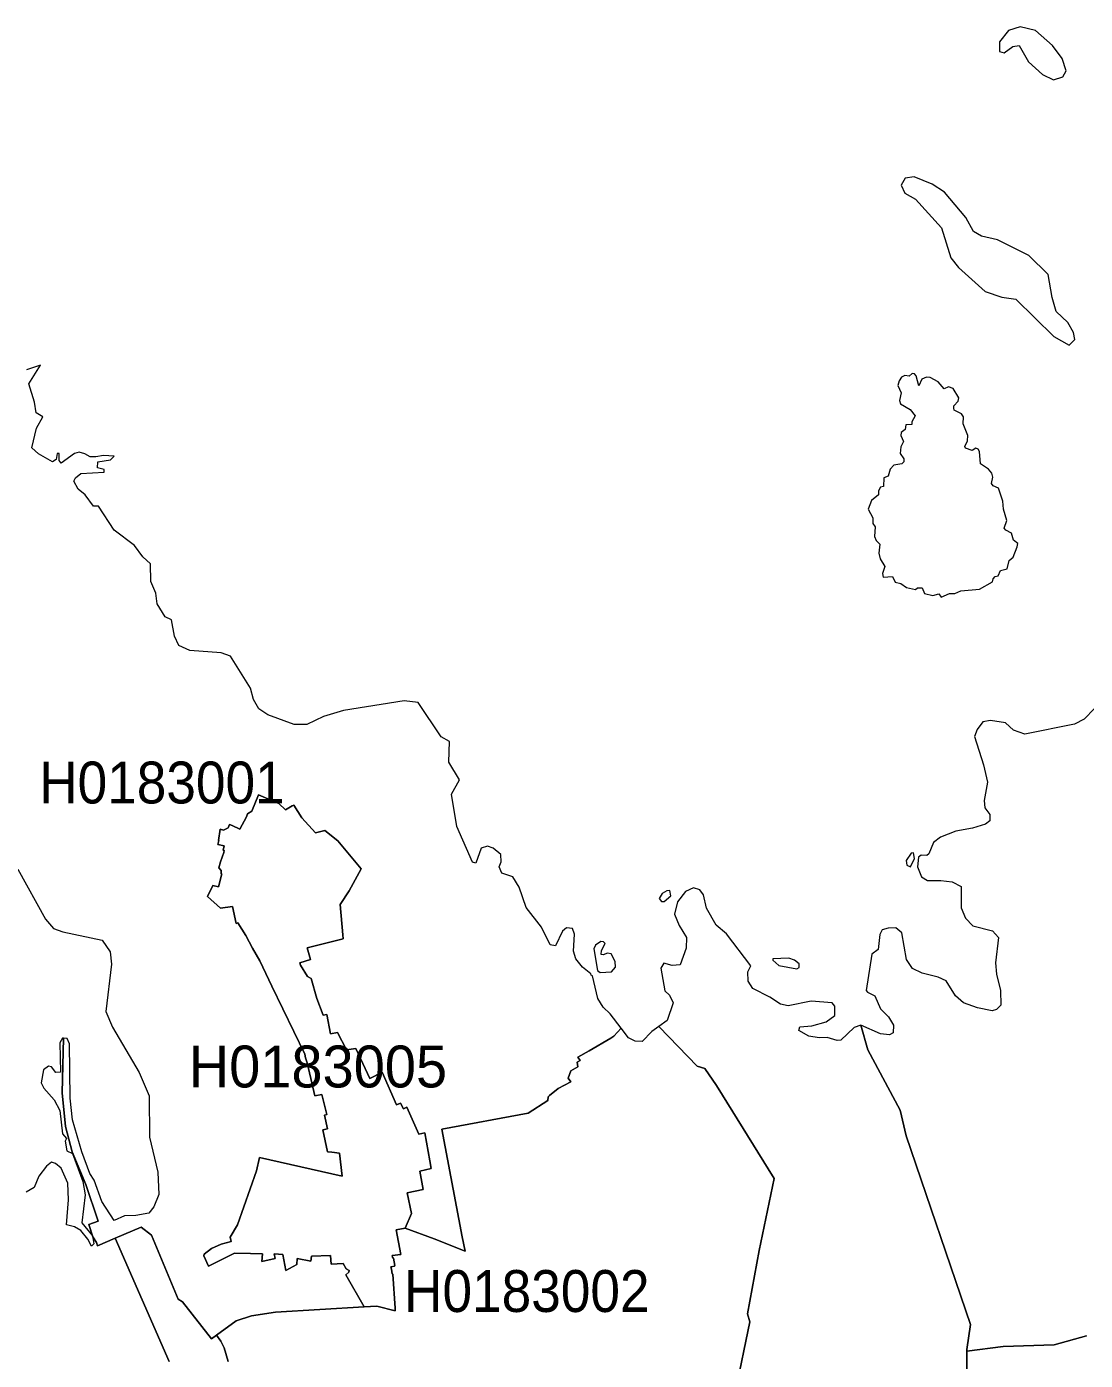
# Model space of a CAD drawing. Extents: x 369010 to 739155, y 6377141 to 6616555.
# Drawn here: x 472785 to 475314, y 6533160 to 6536345 of the extents above; entities that cross this region are included whole.
import ezdxf
from ezdxf.enums import TextEntityAlignment as Align

# ---------------------------------------------------------------- set-up
doc = ezdxf.new("R2010")
doc.units = 0
doc.header["$LTSCALE"] = 40
doc.layers.add('1', color=7, linetype='Continuous', lineweight=13)
doc.layers.add('2', color=7, linetype='Continuous')

msp = doc.modelspace()

# ---------------------------------------------------------------- linework, layer by layer
at = {"layer": '1'}
for points in [[(475194.76, 6536336.3), (475158.18, 6536345.08), (475129.88, 6536336.3), (475108.2, 6536309.16), (475108.2, 6536285.66), (475119.95, 6536282.51), (475140.31, 6536298.07), (475155.7, 6536299.89), (475178.04, 6536261), (475211.31, 6536231.21), (475237.29, 6536218.3), (475259.64, 6536225.09), (475267.58, 6536239.98), (475257.81, 6536268.94), (475235.47, 6536299.89)], [(474904.46, 6535986.43), (474883.44, 6535982.95), (474873.51, 6535966.24), (474882.62, 6535947.87), (474907.77, 6535932.81), (474970, 6535864.45), (474992.02, 6535792.95), (475010.72, 6535769.95), (475074.6, 6535712.85), (475113.99, 6535699.28), (475147.42, 6535693.98), (475238.45, 6535605.11), (475275.03, 6535584.58), (475288.6, 6535598.16), (475285.62, 6535614.87), (475271.88, 6535638.54), (475244.08, 6535664.69), (475234.31, 6535698.12), (475224.38, 6535753.56), (475178.87, 6535798.42), (475103.73, 6535836.32), (475065.66, 6535844.59), (475046.63, 6535856.01), (475028.43, 6535889.44), (474976.79, 6535949.52), (474947.99, 6535969.22)], [(474903.3, 6534372.1), (474897.35, 6534371.11), (474885.27, 6534354.06), (474887.58, 6534342.64), (474896.02, 6534338.51), (474905.46, 6534359.03)], [(474321.39, 6534282.07), (474314.28, 6534281.74), (474302.69, 6534274.95), (474295.57, 6534262.87), (474300.87, 6534255.92), (474307.99, 6534255.59), (474323.38, 6534269.66)], [(474162.67, 6534159.93), (474156.22, 6534160.09), (474143.81, 6534151.98), (474139.34, 6534143.21), (474148.11, 6534091.41), (474154.56, 6534086.11), (474181.87, 6534088.1), (474191.14, 6534099.19), (474190.31, 6534112.43), (474180.88, 6534130.96), (474172.44, 6534132.95), (474161.85, 6534128.31), (474157.05, 6534129.47), (474157.87, 6534138.58), (474166.98, 6534155.95)], [(474624.6, 6534094.88), (474630.39, 6534098.52), (474630.22, 6534107.46), (474619.13, 6534115.57), (474605.4, 6534120.7), (474567.5, 6534119.05), (474567.33, 6534115.74), (474581.23, 6534103.32)]]:
    msp.add_lwpolyline(points, close=True, dxfattribs=at)
for points in [[(473249.75, 6534850.08), (473174.45, 6534855.37), (473148.8, 6534867.29), (473138.2, 6534889.8), (473130.92, 6534928.36), (473115.86, 6534935.48), (473096.5, 6534966.43), (473093.85, 6534991.91), (473081.6, 6535020.22), (473080.61, 6535062.58), (473062.57, 6535078.8), (473042.21, 6535106.28), (472993.72, 6535142.36), (472956.65, 6535200.12), (472944.4, 6535199.79), (472924.54, 6535227.43), (472907.82, 6535240.67), (472897.56, 6535259.7), (472902.03, 6535267.64), (472914.77, 6535278.24), (472970.38, 6535280.88), (472970.38, 6535287.5), (472954, 6535291.81), (472955.32, 6535305.54), (472985.44, 6535310.34), (472993.72, 6535319.61), (472968.56, 6535321.43), (472950.36, 6535317.63), (472936.62, 6535317.63), (472923.88, 6535325.07), (472910.14, 6535328.72), (472899.55, 6535325.57), (472867.44, 6535303.06), (472862.64, 6535308.85), (472862.64, 6535326.07), (472858.17, 6535326.07), (472855.52, 6535311.83), (472847.08, 6535306.21), (472813.65, 6535324.74), (472797.27, 6535339.31), (472808.69, 6535386.48), (472823.75, 6535413.29), (472807.86, 6535422.56), (472803.89, 6535448.21), (472789.82, 6535492.23), (472818.45, 6535536.42), (472785.02, 6535525.83)], [(474809.8, 6535127.79), (474813.77, 6535118.36), (474822.7, 6535109.26), (474820.55, 6535087.74), (474823.2, 6535074.17), (474834.29, 6535055.96), (474829.16, 6535039.08), (474830.98, 6535030.15), (474853.32, 6535031.97), (474859.28, 6535018.56), (474873.02, 6535015.42), (474886.26, 6535005.82), (474907.61, 6535000.69), (474912.57, 6535005.16), (474923.83, 6535004.66), (474929.45, 6534991.75), (474949.65, 6534986.62), (474963.38, 6534990.76), (474969.34, 6534982.65), (474989.04, 6534991.58), (475001.78, 6534991.58), (475016.51, 6534998.2), (475060.7, 6535001.85), (475091.81, 6535019.72), (475093.14, 6535026.34), (475098.27, 6535031.97), (475105.05, 6535033.79), (475110.68, 6535046.37), (475127.07, 6535050.67), (475131.37, 6535070.53), (475141.47, 6535078.47), (475150.57, 6535103.3), (475152.39, 6535110.75), (475142.13, 6535119.02), (475137.49, 6535135.9), (475123.26, 6535142.52), (475119.78, 6535147.32), (475125.74, 6535166.02), (475117.96, 6535192.67), (475116.14, 6535212.04), (475106.21, 6535243.32), (475093.3, 6535248.61), (475089.17, 6535253.91), (475092.97, 6535269.13), (475090.16, 6535278.57), (475082.21, 6535288), (475062.85, 6535301.24), (475060.7, 6535330.87), (475057.89, 6535335.83), (475052.09, 6535338.15), (475042.99, 6535332.85), (475027.43, 6535338.48), (475025.78, 6535342.62), (475032.4, 6535355.86), (475032.73, 6535368.93), (475021.64, 6535396.9), (475022.14, 6535413.45), (475018, 6535420.57), (475000.29, 6535429.01), (474999.13, 6535433.98), (474999.63, 6535439.77), (475009.89, 6535450.69), (475011.71, 6535458.97), (474997.48, 6535480.81), (474986.39, 6535485.12), (474976.13, 6535479.99), (474962.06, 6535497.03), (474942.86, 6535507.63), (474934.25, 6535508.45), (474923.17, 6535503.32), (474915.88, 6535487.43), (474909.76, 6535511.27), (474905.79, 6535516.4), (474899.99, 6535516.56), (474892.38, 6535510.77), (474882.12, 6535512.42), (474874.67, 6535508.12), (474868.55, 6535499.18), (474866.07, 6535488.59), (474874.01, 6535470.88), (474869.87, 6535452.68), (474872.02, 6535444.57), (474895.03, 6535430.5), (474906.78, 6535416.1), (474899.17, 6535401.7), (474899.33, 6535394.92), (474884.77, 6535394.59), (474882.95, 6535382.84), (474873.35, 6535375.72), (474873.18, 6535368.6), (474879.31, 6535354.7), (474872.85, 6535341.46), (474871.53, 6535325.9), (474880.3, 6535313.16), (474880.13, 6535305.71), (474875.17, 6535301.41), (474855.81, 6535297.77), (474847.53, 6535288.33), (474842.4, 6535271.29), (474832.3, 6535267.31)], [(474832.3, 6535267.31), (474831.31, 6535247.12), (474824.53, 6535245.14), (474819.56, 6535236.86), (474819.39, 6535227.1), (474803.18, 6535213.36), (474794.9, 6535192.67), (474805.99, 6535171.98), (474806.15, 6535158.91), (474811.45, 6535150.96), (474809.8, 6535127.79)], [(473528.3, 6534400.57), (473584.24, 6534333.71), (473555.61, 6534281.24), (473533.76, 6534248.97), (473540.05, 6534175.98), (473540.71, 6534166.88), (473455.14, 6534145.03), (473463.09, 6534117.23), (473437.6, 6534109.78), (473439.42, 6534104.15), (473455.64, 6534076.68), (473464.25, 6534071.71), (473478.32, 6534024.05), (473493.21, 6533984.66), (473501.98, 6533986.15), (473511.09, 6533940.14), (473527.3, 6533943.28), (473548.82, 6533901.57), (473571.33, 6533905.22), (473604.43, 6533833.55), (473634.39, 6533848.61), (473668.31, 6533770.33), (473678.24, 6533774.63), (473685.03, 6533761.06), (473693.14, 6533764.7), (473721.94, 6533700.49), (473736.01, 6533703.3), (473747.76, 6533636.93), (473750.9, 6533618.73), (473723.92, 6533612.27), (473732.2, 6533568.41), (473693.97, 6533560.31), (473704.23, 6533510.82), (473689.33, 6533475.73), (473758.02, 6533450.74), (473832.49, 6533420.95), (473825.05, 6533455.54), (473776.39, 6533712.07), (473982.61, 6533750.63), (474029.94, 6533780.76), (474030.44, 6533789.53), (474033.42, 6533792.67), (474054.43, 6533809.06), (474084.56, 6533825.28), (474077.94, 6533833.72), (474084.56, 6533851.59), (474101.11, 6533861.03), (474100.11, 6533871.95), (474106.9, 6533876.42), (474101.27, 6533883.87), (474128.42, 6533899.42), (474179.89, 6533929.88), (474187.17, 6533934.18), (474204.71, 6533953.54), (474178.56, 6533987.64), (474161.85, 6534003.52), (474149.43, 6534024.71), (474136.52, 6534078.33), (474133.55, 6534080.15), (474132.55, 6534082.97), (474112.36, 6534099.35), (474096.47, 6534118.72), (474090.85, 6534137.25), (474093.82, 6534178.13), (474088.53, 6534191.21), (474074.46, 6534192.86), (474065.19, 6534184.92), (474047.98, 6534150), (474035.24, 6534152.15), (474014.55, 6534195.01), (473978.3, 6534241.35), (473961.09, 6534289.85), (473946.53, 6534314.51), (473919.88, 6534323.94), (473913.59, 6534338.51), (473918.56, 6534350.42), (473917.56, 6534367.96), (473899.52, 6534383.52), (473885.95, 6534387.83), (473870.39, 6534383.03), (473858.15, 6534347.28), (473849.71, 6534349.92), (473812.63, 6534434.99), (473799.89, 6534512.62), (473818.43, 6534546.21), (473793.27, 6534588.91), (473795.09, 6534637.9), (473775.23, 6534649.49), (473719.95, 6534731.58), (473686.52, 6534735.55), (473541.37, 6534711.88), (473494.2, 6534698.15), (473454.48, 6534678.28), (473423.53, 6534678.28), (473361.3, 6534701.46), (473339.79, 6534716.02), (473326.55, 6534738.53), (473319.93, 6534765.51), (473271.77, 6534841.8), (473249.75, 6534850.08)], [(475335.1, 6534716.85), (475310.44, 6534691.19), (475287.44, 6534679.28), (475168.77, 6534655.94), (475141.96, 6534665.21), (475122.93, 6534682.75), (475087.18, 6534688.55), (475068.64, 6534685.07), (475055.24, 6534667.03), (475049.11, 6534649.98), (475070.3, 6534582.46), (475079.57, 6534540.59), (475071.62, 6534496.89), (475073.77, 6534480.01), (475085.19, 6534463.79), (475085.69, 6534448.73), (475075.1, 6534440.79), (475044.31, 6534431.19), (475004.59, 6534424.07)], [(472933.31, 6533484.84), (472943.24, 6533455.21), (472951.68, 6533441.47), (472954.33, 6533434.03), (472996.7, 6533452.4), (473058.27, 6533478.38), (473082.93, 6533458.85), (473147.14, 6533306.42), (473157.4, 6533300.13), (473226.42, 6533211.42), (473238.17, 6533220.03), (473285.34, 6533254.78), (473321.75, 6533266.7), (473379.01, 6533275.31), (473590.86, 6533287.72), (473547.33, 6533364.68), (473554.12, 6533370.8), (473555.27, 6533374.61), (473548.49, 6533378.91), (473541.21, 6533391.33), (473511.91, 6533390), (473510.75, 6533410.86), (473465.24, 6533409.2), (473463.59, 6533396.79), (473431.31, 6533403.24), (473430.32, 6533389.01), (473403.67, 6533374.61), (473396.56, 6533412.68), (473376.03, 6533414.66), (473378.19, 6533403.74), (473346.57, 6533396.46), (473347.9, 6533414.83), (473319.76, 6533415.32), (473281.03, 6533416.15), (473219.47, 6533385.37), (473207.88, 6533410.03), (473209.21, 6533413.67), (473226.42, 6533427.07), (473249.42, 6533437.67), (473273.75, 6533444.29), (473271.27, 6533454.55), (473288.81, 6533483.51), (473333.83, 6533612.77), (473341.28, 6533645.04), (473538.23, 6533600.36), (473532.1, 6533654.81), (473513.9, 6533657.29), (473503.64, 6533658.45), (473492.38, 6533710.75), (473503.14, 6533713.23), (473496.52, 6533745.84), (473502.15, 6533747.16), (473489.74, 6533794.99), (473473.52, 6533791.51), (473463.92, 6533833.06), (473454.65, 6533870.79), (473450.84, 6533883.04), (473449.52, 6533891.15), (473370.41, 6534053.84), (473341.94, 6534114.08), (473324.73, 6534144.37), (473308.67, 6534174.82), (473289.31, 6534205.27), (473285.5, 6534203.12), (473276.73, 6534243.84), (473247.93, 6534239.7), (473216.82, 6534267.67), (473229.89, 6534294.32), (473242.97, 6534291.17), (473251.08, 6534321.79), (473249.42, 6534322.12), (473249.42, 6534329.9), (473244.29, 6534336.68), (473247.6, 6534350.42), (473256.04, 6534373.1), (473256.71, 6534378.06), (473254.55, 6534378.23), (473257.04, 6534389.15), (473241.81, 6534392.13), (473243.63, 6534401.4), (473242.97, 6534401.56), (473247.44, 6534428.87), (473255.05, 6534426.06), (473266.14, 6534431.85), (473269.61, 6534440.12), (473276.07, 6534437.81), (473275.9, 6534437.31), (473294.28, 6534428.37), (473309.83, 6534458.16), (473312.15, 6534465.28), (473322.91, 6534471.9), (473338.46, 6534510.79), (473386.96, 6534489.78), (473402.85, 6534474.71), (473419.4, 6534484.48), (473423.2, 6534486.3), (473442.07, 6534455.85), (473474.67, 6534419.93), (473497.51, 6534425.39), (473528.3, 6534400.57)], [(473528.3, 6534400.57), (473497.51, 6534425.39), (473474.67, 6534419.93), (473442.07, 6534455.85), (473423.2, 6534486.3), (473419.4, 6534484.48), (473402.85, 6534474.71), (473386.96, 6534489.78), (473338.46, 6534510.79), (473322.91, 6534471.9), (473312.15, 6534465.28), (473309.83, 6534458.16), (473294.28, 6534428.37), (473275.9, 6534437.31), (473276.07, 6534437.81), (473269.61, 6534440.12), (473266.14, 6534431.85), (473255.05, 6534426.06), (473247.44, 6534428.87), (473242.97, 6534401.56), (473243.63, 6534401.4), (473241.81, 6534392.13), (473257.04, 6534389.15), (473254.55, 6534378.23), (473256.71, 6534378.06), (473256.04, 6534373.1), (473247.6, 6534350.42), (473244.29, 6534336.68), (473249.42, 6534329.9), (473249.42, 6534322.12), (473251.08, 6534321.79), (473242.97, 6534291.17), (473229.89, 6534294.32), (473216.82, 6534267.67), (473247.93, 6534239.7)], [(473247.93, 6534239.7), (473276.73, 6534243.84), (473285.5, 6534203.12), (473289.31, 6534205.27), (473308.67, 6534174.82), (473324.73, 6534144.37), (473341.94, 6534114.08), (473370.41, 6534053.84), (473449.52, 6533891.15), (473450.84, 6533883.04), (473454.65, 6533870.79), (473463.92, 6533833.06), (473473.52, 6533791.51), (473489.74, 6533794.99), (473502.15, 6533747.16), (473496.52, 6533745.84), (473503.14, 6533713.23), (473492.38, 6533710.75), (473503.64, 6533658.45), (473513.9, 6533657.29), (473532.1, 6533654.81), (473538.23, 6533600.36), (473341.28, 6533645.04), (473333.83, 6533612.77), (473288.81, 6533483.51), (473271.27, 6533454.55), (473273.75, 6533444.29), (473249.42, 6533437.67), (473226.42, 6533427.07), (473209.21, 6533413.67), (473207.88, 6533410.03), (473219.47, 6533385.37), (473281.03, 6533416.15), (473319.76, 6533415.32), (473347.9, 6533414.83), (473346.57, 6533396.46), (473378.19, 6533403.74), (473376.03, 6533414.66), (473396.56, 6533412.68), (473403.67, 6533374.61), (473430.32, 6533389.01), (473431.31, 6533403.24), (473463.59, 6533396.79), (473465.24, 6533409.2), (473510.75, 6533410.86), (473511.91, 6533390), (473541.21, 6533391.33), (473548.49, 6533378.91), (473555.27, 6533374.61), (473554.12, 6533370.8), (473547.33, 6533364.68), (473590.86, 6533287.72), (473621.64, 6533289.71), (473665.34, 6533278.29), (473664.84, 6533284.91), (473659.87, 6533366), (473657.89, 6533366.83), (473656.07, 6533377.59), (473654.74, 6533383.22), (473663.68, 6533385.04), (473664.51, 6533386.36), (473661.2, 6533404.4), (473658.88, 6533406.06), (473658.05, 6533410.36), (473679.07, 6533412.68), (473667.82, 6533471.76), (473689.33, 6533475.73), (473704.23, 6533510.82), (473693.97, 6533560.31), (473732.2, 6533568.41), (473723.92, 6533612.27), (473750.9, 6533618.73), (473747.76, 6533636.93), (473736.01, 6533703.3), (473721.94, 6533700.49), (473693.14, 6533764.7), (473685.03, 6533761.06), (473678.24, 6533774.63), (473668.31, 6533770.33), (473634.39, 6533848.61), (473604.43, 6533833.55), (473571.33, 6533905.22), (473548.82, 6533901.57), (473527.3, 6533943.28), (473511.09, 6533940.14), (473501.98, 6533986.15), (473493.21, 6533984.66), (473478.32, 6534024.05), (473464.25, 6534071.71), (473455.64, 6534076.68), (473439.42, 6534104.15), (473437.6, 6534109.78), (473463.09, 6534117.23), (473455.14, 6534145.03), (473540.71, 6534166.88), (473540.05, 6534175.98), (473533.76, 6534248.97), (473555.61, 6534281.24), (473584.24, 6534333.71), (473528.3, 6534400.57)], [(475004.59, 6534424.07), (474967.52, 6534409.51), (474951.14, 6534397.09), (474939.72, 6534369.45), (474935.25, 6534365.81), (474921.68, 6534366.81), (474915.39, 6534361.51), (474912.74, 6534339), (474922.01, 6534314.67), (474936.24, 6534305.9), (474968.35, 6534306.23), (474995.66, 6534302.76), (475017.34, 6534291.67), (475017.34, 6534240.53), (475027.1, 6534215.87), (475045.14, 6534198.16), (475091.81, 6534185.74), (475106.38, 6534170.35), (475098.93, 6534109.12), (475101.08, 6534082.64), (475110.85, 6534043.41), (475111.67, 6534008.49), (475101.58, 6533998.39), (475090.99, 6533994.75), (475056.23, 6534002.37), (475022.63, 6534013.79), (475003.6, 6534030.5), (474980.76, 6534066.25), (474962.06, 6534075.19), (474923.66, 6534084.79), (474900.33, 6534096.21), (474886.59, 6534117.39), (474875.5, 6534180.95), (474860.94, 6534193.36), (474842.9, 6534192.36), (474828, 6534188.06), (474823.04, 6534177.47), (474818.73, 6534141.72), (474803.84, 6534130.47)], [(472764.33, 6534333.54), (472830.04, 6534213.71), (472849.4, 6534191.21), (472871.74, 6534183.26), (472965.42, 6534163.9), (472984.78, 6534135.6), (472987.93, 6534106.63), (472974.02, 6533993.26), (472990.08, 6533955.69), (473053.8, 6533847.45), (473077.8, 6533791.85), (473078.46, 6533693.37), (473098.15, 6533609.29), (473100.3, 6533556.33), (473088.55, 6533526.87), (473076.8, 6533511.98), (473045.85, 6533506.02), (473018.55, 6533505.52), (472994.38, 6533494.27), (472964.43, 6533539.78), (472946.22, 6533590.59), (472936.12, 6533606.65), (472916.93, 6533658.12), (472894.42, 6533734.58), (472888.96, 6533786.55), (472886.97, 6533915.97), (472881.51, 6533928.88), (472872.74, 6533929.38), (472870.09, 6533799.46), (472877.54, 6533718.86), (472893.92, 6533658.28), (472926.69, 6533580.33), (472955.49, 6533492.28), (472933.31, 6533484.84)], [(474603.41, 6534007.17), (474585.37, 6534010.64), (474559.72, 6534027.85), (474519.67, 6534048.21), (474508.58, 6534065.75), (474507.75, 6534087.93), (474514.37, 6534102), (474456.61, 6534179.12), (474431.45, 6534199.48), (474408.45, 6534240.03), (474401.83, 6534271.81), (474392.56, 6534284.05), (474377.66, 6534288.52), (474358.63, 6534280.25), (474339.6, 6534255.09), (474332.65, 6534225.96), (474343.24, 6534198.99), (474361.28, 6534170.35), (474359.96, 6534144.7), (474346.22, 6534104.65), (474326.52, 6534103.32), (474306.66, 6534108.62), (474300.04, 6534097.03), (474308.81, 6534042.42), (474320.73, 6534032.65), (474329.5, 6534014.12), (474314.94, 6533971.91), (474294.91, 6533957.68)], [(474803.84, 6534130.47), (474790.27, 6534043.58), (474793.08, 6534039.44), (474810.79, 6534030.5), (474824.03, 6534000.05), (474843.72, 6533980.35), (474855.31, 6533960.49), (474854.32, 6533942.29), (474846.04, 6533937.49), (474824.03, 6533940.14), (474777.19, 6533960.49), (474794.07, 6533901.91), (474870.87, 6533757.75), (474885.93, 6533696.18), (475039.02, 6533246.01), (475030.25, 6533186.1), (475030.41, 6533182.46), (475117.3, 6533193.38), (475239.44, 6533197.02), (475316.24, 6533219.04)], [(475034.05, 6532841.36), (475030.41, 6533182.46), (475030.25, 6533186.1), (475039.02, 6533246.01), (474885.93, 6533696.18), (474870.87, 6533757.75), (474794.07, 6533901.91), (474777.19, 6533960.49), (474761.8, 6533954.7), (474729.53, 6533925.08), (474720.75, 6533924.25), (474696.92, 6533930.87), (474677.56, 6533930.04), (474653.23, 6533934.34), (474629.4, 6533947.58), (474631.71, 6533956.85), (474660.35, 6533959.17), (474694.27, 6533968.44), (474714.96, 6533983.83), (474715.46, 6534005.84), (474708.84, 6534014.28), (474658.52, 6534017.76), (474603.41, 6534007.17)], [(474478.29, 6533086.63), (474511.89, 6533252.14), (474506.92, 6533271.17), (474534.89, 6533422.44), (474570.48, 6533594.73), (474432.28, 6533816.51), (474404.81, 6533857.38), (474386.27, 6533863.01), (474295.91, 6533956.52), (474294.91, 6533957.68), (474277.87, 6533945.76), (474255.03, 6533921.93), (474238.64, 6533922.43), (474222.42, 6533930.37), (474204.71, 6533953.54), (474187.17, 6533934.18), (474179.89, 6533929.88), (474128.42, 6533899.42), (474101.27, 6533883.87), (474106.9, 6533876.42), (474100.11, 6533871.95), (474101.11, 6533861.03), (474084.56, 6533851.59), (474077.94, 6533833.72), (474084.56, 6533825.28), (474054.43, 6533809.06), (474033.42, 6533792.67), (474030.44, 6533789.53), (474029.94, 6533780.76), (473982.61, 6533750.63), (473776.39, 6533712.07), (473825.05, 6533455.54), (473832.49, 6533420.95), (473758.02, 6533450.74), (473689.33, 6533475.73), (473667.82, 6533471.76), (473679.07, 6533412.68), (473658.05, 6533410.36), (473658.88, 6533406.06), (473661.2, 6533404.4), (473664.51, 6533386.36), (473663.68, 6533385.04), (473654.74, 6533383.22), (473656.07, 6533377.59), (473657.89, 6533366.83), (473659.87, 6533366), (473664.84, 6533284.91), (473665.34, 6533278.29), (473621.64, 6533289.71), (473590.86, 6533287.72), (473379.01, 6533275.31), (473321.75, 6533266.7), (473285.34, 6533254.78), (473238.17, 6533220.03), (473248.43, 6533205.96), (473256.87, 6533189.91), (473266.47, 6533157.3)], [(474294.91, 6533957.68), (474295.91, 6533956.52), (474386.27, 6533863.01), (474404.81, 6533857.38), (474432.28, 6533816.51), (474570.48, 6533594.73), (474534.89, 6533422.44), (474506.92, 6533271.17), (474511.89, 6533252.14), (474478.29, 6533086.63)], [(473125.46, 6533157.47), (472996.7, 6533452.4), (472954.33, 6533434.03), (472951.68, 6533441.47), (472943.24, 6533455.21), (472933.31, 6533484.84), (472955.49, 6533492.28), (472926.69, 6533580.33), (472893.92, 6533658.28), (472877.54, 6533718.86), (472870.09, 6533799.46), (472872.74, 6533929.38), (472870.75, 6533929.38), (472864.46, 6533918.12), (472865.45, 6533848.61), (472854.86, 6533847.45), (472844.1, 6533860.86), (472837.15, 6533862.52), (472825.4, 6533853.91), (472819.44, 6533822.96), (472826.4, 6533810.55), (472851.06, 6533782.74), (472864.46, 6533756.59), (472870.25, 6533701.48), (472879.85, 6533690.23), (472877.21, 6533683.27), (472881.01, 6533660.77), (472894.42, 6533654.31), (472919.57, 6533586.95), (472924.87, 6533555.84), (472916.93, 6533488.97), (472942.58, 6533457.36), (472945.23, 6533438.16), (472939.93, 6533432.7), (472931.32, 6533449.91), (472914.11, 6533470.27), (472899.22, 6533479.37), (472880.52, 6533484.17), (472885.31, 6533543.59), (472883.16, 6533583.14), (472867.11, 6533619.06), (472853.87, 6533630.64), (472844.27, 6533633.46), (472832.02, 6533623.69), (472813.82, 6533599.7), (472802.56, 6533573.38), (472783.86, 6533561.63)], [(473266.47, 6533157.3), (473256.87, 6533189.91), (473248.43, 6533205.96), (473238.17, 6533220.03), (473226.42, 6533211.42), (473157.4, 6533300.13), (473147.14, 6533306.42), (473082.93, 6533458.85), (473058.27, 6533478.38), (472996.7, 6533452.4), (473125.46, 6533157.47)], [(475316.24, 6533219.04), (475239.44, 6533197.02), (475117.3, 6533193.38), (475030.41, 6533182.46), (475034.05, 6532841.36), (475045.31, 6532782.93), (475052.59, 6532763.73), (475052.59, 6532761.91), (475056.07, 6532753.14), (475122.1, 6532580.69), (475157.85, 6532346.83), (475170.76, 6532279.64), (475179.86, 6532197.05), (475180.19, 6531978.09), (475145.27, 6531862.57), (475150.07, 6531765.75), (475141.8, 6531664.62), (475187.14, 6531559.2), (475224.38, 6531333.95), (475432.92, 6530912.9)]]:
    msp.add_lwpolyline(points, dxfattribs=at)

# ---------------------------------------------------------------- texts
at = {"layer": '2', "width": 0.95}
for s, p in [('H0183001', (473108.08, 6534490.11)), ('H0183002', (473979.55, 6533275.78))]:
    msp.add_text(s, height=100, dxfattribs=at).set_placement(p, align=Align.CENTER)
at = {"layer": '2'}
msp.add_text('H0183005', height=100, dxfattribs=at).set_placement((473480.64, 6533811.95), align=Align.CENTER)

doc.saveas('drawing.dxf')
